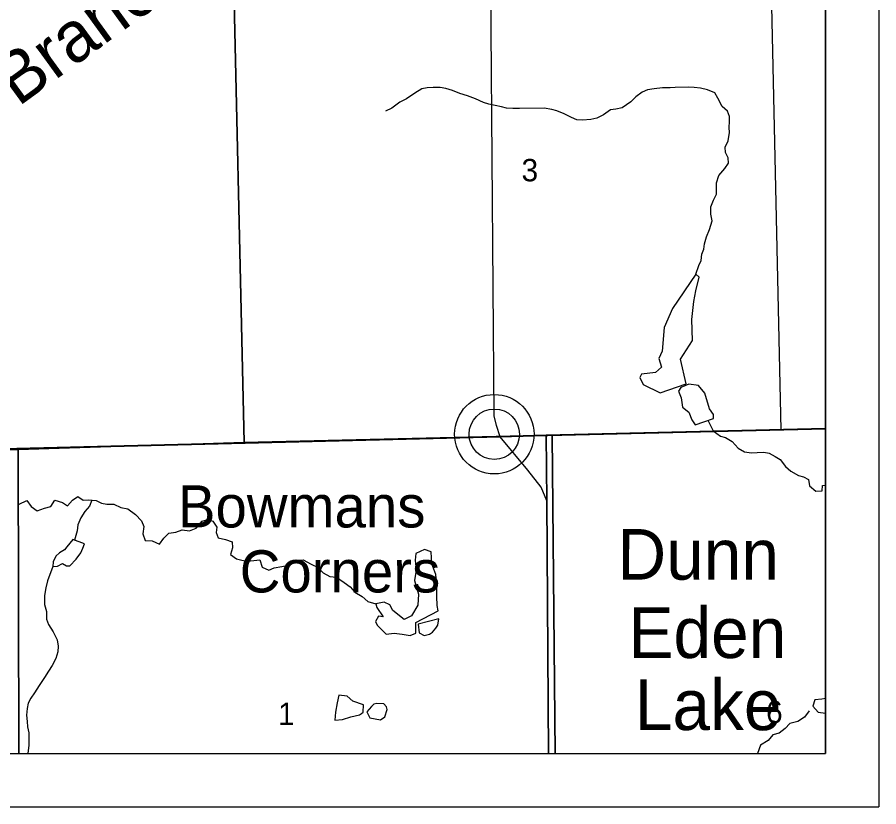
# Model space of a CAD drawing. Extents: x 0 to 34, y 0 to 22.
# Drawn here: x 8.73 to 10.344, y 13.024 to 14.503 of the extents above; entities that cross this region are included whole.
import ezdxf

# ---------------------------------------------------------------- set-up
doc = ezdxf.new("R2010")
doc.units = 0
for name, color, linetype in [('GM_X_Corporation', 7, 'Continuous'), ('GM_X_County_Road', 7, 'Continuous'), ('GM_X_Minor_Lake', 7, 'Continuous'), ('GM_X_Minor_Lake_Text', 7, 'Continuous'), ('GM_X_Minor_River', 7, 'Continuous'), ('GM_X_Minor_River_Text', 7, 'Continuous'), ('GM_X_Section_Text', 7, 'Continuous'), ('GM_X_State_Route', 7, 'Continuous'), ('GM_X_Unincorporated', 7, 'Continuous'), ('GM_X_Unincorporated_Location', 7, 'Continuous'), ('GM_X_Unincorporated_Text', 7, 'Continuous'), ('SH_Data', 7, 'Continuous')]:
    doc.layers.add(name, color=color, linetype=linetype)

msp = doc.modelspace()

# ---------------------------------------------------------------- linework, layer by layer
at = {"layer": 'GM_X_Corporation'}
msp.add_lwpolyline([(7.068, 16.109), (7.0714, 16.0063), (7.0745, 15.896), (7.0787, 15.766), (7.0827, 15.6404), (7.0859, 15.5239), (7.0914, 15.3396), (7.0961, 15.1801), (7.0965, 15.1593), (7.1012, 14.6522), (7.1045, 14.5502), (7.1291, 13.6578), (8.1719, 13.6806), (8.628, 13.6922), (9.6344, 13.7177), (9.7208, 13.7198), (10.2438, 13.7323), (10.2438, 18.8341)], dxfattribs=at)
for points in [[(10.2438, 13.7318), (10.2438, 14.7535), (10.1377, 14.7507), (10.1605, 13.7298)], [(9.132, 14.7248), (10.1377, 14.7507), (10.1605, 13.7298), (9.7319, 13.7196), (9.155, 13.7064)], [(8.1182, 14.6962), (9.132, 14.7248), (9.155, 13.7064), (8.7319, 13.6926), (8.142, 13.6801)], [(3.5203, 13.1239), (9.7254, 13.1239), (9.7218, 13.5975), (9.7208, 13.7198), (9.6344, 13.7177), (8.628, 13.6922), (8.1719, 13.6806), (7.1291, 13.6578), (7.1049, 13.6572), (5.8662, 13.6357), (5.5741, 13.6306), (4.9278, 13.619), (3.5133, 13.5939)], [(8.7329, 13.1239), (9.7377, 13.1239), (9.7319, 13.7196), (9.155, 13.7064), (8.7319, 13.6926)], [(9.7254, 13.1239), (10.2438, 13.1239), (10.2438, 13.7323), (9.7208, 13.7198), (9.7218, 13.5975)], [(9.7377, 13.1239), (10.2438, 13.1239), (10.2438, 13.7318), (10.1605, 13.7298), (9.7319, 13.7196)], [(7.6372, 13.1239), (8.7329, 13.1239), (8.7319, 13.6926), (8.142, 13.6801), (7.6279, 13.6693)]]:
    msp.add_lwpolyline(points, close=True, dxfattribs=at)
at = {"layer": 'GM_X_County_Road'}
msp.add_line((9.724, 13.7194), (10.2438, 13.7317), dxfattribs=at)
msp.add_lwpolyline([(8.6282, 13.6916), (9.6346, 13.7171), (9.721, 13.7193), (9.724, 13.7194)], dxfattribs=at)
at = {"layer": 'GM_X_Minor_Lake'}
for points in [[(9.9832, 13.8159), (9.9726, 13.8624), (9.9948, 13.8973), (9.9934, 13.9364), (9.9974, 13.9703), (10.0012, 13.9905), (10.0076, 14.0161), (10.0011, 14.0216), (9.9574, 13.9571), (9.9416, 13.9215), (9.9382, 13.8774), (9.9316, 13.8636), (9.9371, 13.8474), (9.9255, 13.8373), (9.8994, 13.8342), (9.8961, 13.8277), (9.9024, 13.8149), (9.9345, 13.7991)], [(9.9345, 13.7991), (9.9832, 13.8159)], [(10.034, 13.7514), (10.0343, 13.7586), (10.0269, 13.7691), (10.0177, 13.7986), (10.0064, 13.8128), (9.9882, 13.8156), (9.9731, 13.8089), (9.9686, 13.8023), (9.9738, 13.7899), (9.9764, 13.7721), (9.9883, 13.7628), (9.9938, 13.7484), (9.9997, 13.739)], [(9.9997, 13.739), (10.034, 13.7514)], [(8.834, 13.5244), (8.8228, 13.5109), (8.8184, 13.5052), (8.8093, 13.4993), (8.8022, 13.4935), (8.7971, 13.4824), (8.7965, 13.4737), (8.8052, 13.4746), (8.8146, 13.4796), (8.8223, 13.4752), (8.8287, 13.4753), (8.8403, 13.4877), (8.8492, 13.4996), (8.8529, 13.508), (8.8558, 13.5164)], [(8.8558, 13.5164), (8.834, 13.5244)], [(9.5184, 13.3908), (9.5163, 13.4011), (9.5157, 13.4178), (9.5161, 13.439), (9.5138, 13.4588), (9.5067, 13.4788), (9.5052, 13.5015), (9.4929, 13.5055), (9.4767, 13.498), (9.4751, 13.4859), (9.4773, 13.4673), (9.4742, 13.4475), (9.4814, 13.4221), (9.4802, 13.4012), (9.4684, 13.3817), (9.4545, 13.3746), (9.4337, 13.3917), (9.4279, 13.4019), (9.4175, 13.4074), (9.4016, 13.4041), (9.4036, 13.397), (9.4153, 13.3797), (9.4069, 13.3811), (9.401, 13.3707), (9.4042, 13.3639), (9.4208, 13.3471), (9.4359, 13.3489), (9.4508, 13.3472), (9.466, 13.3444), (9.4769, 13.3491), (9.4766, 13.3689)], [(9.4766, 13.3689), (9.5184, 13.3908)], [(9.4808, 13.3659), (9.483, 13.3496), (9.4922, 13.3445), (9.502, 13.3469), (9.5077, 13.3508), (9.514, 13.3581), (9.5177, 13.3639), (9.5194, 13.376)], [(9.5194, 13.376), (9.4808, 13.3659)], [(9.3785, 13.215), (9.3587, 13.2219), (9.3483, 13.2312), (9.3323, 13.2332), (9.3291, 13.2187), (9.326, 13.2008), (9.3251, 13.186), (9.3391, 13.1874), (9.3546, 13.1922), (9.3709, 13.1959)], [(9.3786, 13.215), (9.3587, 13.2219), (9.3483, 13.2312), (9.3323, 13.2332), (9.3291, 13.2187), (9.326, 13.2008), (9.3251, 13.186), (9.3391, 13.1874), (9.3546, 13.1922), (9.3709, 13.1959)], [(10.2438, 13.2268), (10.2371, 13.2252), (10.2242, 13.2242), (10.2202, 13.2124), (10.2303, 13.2011), (10.2438, 13.1994)], [(9.3709, 13.1959), (9.375, 13.1983), (9.3777, 13.2008), (9.3785, 13.215)], [(9.3934, 13.2114), (9.3849, 13.2014), (9.3903, 13.1905), (9.4105, 13.1866), (9.4188, 13.1925), (9.4231, 13.2058), (9.4219, 13.2111), (9.4165, 13.2167)], [(9.4165, 13.2167), (9.4033, 13.217), (9.3981, 13.2162), (9.3934, 13.2114)]]:
    msp.add_lwpolyline(points, dxfattribs=at)
at = {"layer": 'GM_X_Minor_River'}
for points in [[(10.0011, 14.0216), (10.0069, 14.0377), (10.0109, 14.0472), (10.0126, 14.0587), (10.0159, 14.0682), (10.0176, 14.0785), (10.0212, 14.0915), (10.027, 14.1049), (10.0317, 14.1213), (10.0292, 14.1338), (10.029, 14.1478), (10.0341, 14.1601), (10.0396, 14.1712), (10.0398, 14.1826), (10.0396, 14.1924), (10.044, 14.2066), (10.0555, 14.2197), (10.0622, 14.2296), (10.062, 14.2395), (10.0565, 14.2493), (10.056, 14.2596), (10.0619, 14.2714), (10.0639, 14.2866), (10.0634, 14.2965), (10.0643, 14.3072), (10.0645, 14.317), (10.0606, 14.3269), (10.0506, 14.3358), (10.0423, 14.3513), (10.0368, 14.3614), (10.0231, 14.3669), (10.0098, 14.3697), (9.9983, 14.3714), (9.9881, 14.3716), (9.9627, 14.3712), (9.9528, 14.3707), (9.9384, 14.3704), (9.9232, 14.3687), (9.9107, 14.367), (9.9009, 14.3626), (9.8889, 14.3537), (9.8792, 14.344), (9.8634, 14.3331), (9.8513, 14.3307), (9.8415, 14.329), (9.828, 14.32), (9.8156, 14.3138), (9.8046, 14.3109), (9.789, 14.3099), (9.778, 14.3105), (9.7681, 14.3149), (9.7547, 14.3219), (9.7409, 14.3277), (9.7314, 14.3302), (9.7169, 14.3327), (9.671, 14.3319), (9.6581, 14.3317), (9.6467, 14.3327), (9.6368, 14.3348), (9.6132, 14.3397), (9.6032, 14.343), (9.5883, 14.3496), (9.5734, 14.3554), (9.5593, 14.3601), (9.5452, 14.3656), (9.5326, 14.3692), (9.5219, 14.3709), (9.5094, 14.3714), (9.498, 14.3705), (9.4878, 14.3684), (9.475, 14.3606), (9.4593, 14.3497), (9.4468, 14.3435), (9.4318, 14.3322), (9.4198, 14.3267)], [(10.0238, 13.7477), (10.0333, 13.7278), (10.0471, 13.7181), (10.0566, 13.7153), (10.0689, 13.7079), (10.0805, 13.6955), (10.0924, 13.6885), (10.1057, 13.6868), (10.1163, 13.6877), (10.1285, 13.6879), (10.1387, 13.6862), (10.1495, 13.6799), (10.1591, 13.6744), (10.1688, 13.6612), (10.1788, 13.6523), (10.1933, 13.6446), (10.2029, 13.6417), (10.2124, 13.6369), (10.2138, 13.6248), (10.2261, 13.6151), (10.2375, 13.6156), (10.2381, 13.6259), (10.2438, 13.626)], [(8.7334, 13.5904), (8.7477, 13.5978), (8.7563, 13.5862), (8.7674, 13.578), (8.781, 13.5832), (8.7931, 13.586), (8.8005, 13.5979), (8.8146, 13.594), (8.8242, 13.5873), (8.8335, 13.5981), (8.8437, 13.6051), (8.8533, 13.5984), (8.8628, 13.5986), (8.8776, 13.5977), (8.8875, 13.5925), (8.8978, 13.5908), (8.9111, 13.5906), (8.9241, 13.5844), (8.9374, 13.5819), (8.9517, 13.5711), (8.9629, 13.5592), (8.9672, 13.5486), (8.9655, 13.5353), (8.9699, 13.5228), (8.9825, 13.5219), (8.9962, 13.516), (9.0044, 13.5268), (9.0141, 13.5361), (9.027, 13.5382), (9.0391, 13.5429), (9.0524, 13.5405), (9.0652, 13.546), (9.0764, 13.5587), (9.087, 13.562), (9.0965, 13.5591), (9.1039, 13.5478), (9.1025, 13.5379), (9.1061, 13.5273), (9.1198, 13.5245), (9.1328, 13.5202), (9.133, 13.5091), (9.1294, 13.4966), (9.1409, 13.488), (9.1509, 13.4855), (9.1604, 13.4841), (9.1733, 13.4851), (9.1846, 13.4861), (9.189, 13.4728), (9.2013, 13.4673), (9.2111, 13.4717), (9.2255, 13.4742), (9.2357, 13.4759), (9.2522, 13.4856), (9.2655, 13.4862), (9.2804, 13.4781), (9.2938, 13.4719), (9.3031, 13.4622), (9.3157, 13.4552), (9.3283, 13.4538), (9.3425, 13.4438), (9.3536, 13.436), (9.3625, 13.4259), (9.376, 13.4178), (9.3864, 13.4081), (9.4016, 13.4041)], [(8.8697, 13.5981), (8.8656, 13.5872), (8.8567, 13.5768), (8.8493, 13.5653), (8.8434, 13.5519), (8.8424, 13.5409), (8.8372, 13.5232)], [(8.7965, 13.4737), (8.7867, 13.4473), (8.7835, 13.4339), (8.7811, 13.4198), (8.7813, 13.4028), (8.785, 13.3899), (8.7848, 13.3751), (8.7884, 13.3653), (8.797, 13.3514), (8.8045, 13.3363), (8.8069, 13.3246), (8.806, 13.3143), (8.8024, 13.3017), (8.7954, 13.2883), (8.7883, 13.2779), (8.7809, 13.266), (8.7713, 13.251), (8.7621, 13.2372), (8.7554, 13.2272), (8.7506, 13.2177), (8.7485, 13.2081), (8.7476, 13.1952), (8.7485, 13.1838), (8.7494, 13.1736), (8.7515, 13.1626), (8.7517, 13.1504), (8.7515, 13.1387), (8.7506, 13.1292), (8.7498, 13.1239)], [(10.2135, 13.2035), (10.2046, 13.192), (10.1922, 13.1834), (10.1775, 13.1801), (10.1685, 13.1705), (10.1573, 13.1616), (10.1456, 13.1587), (10.1366, 13.148), (10.1223, 13.1394), (10.1164, 13.1239)]]:
    msp.add_lwpolyline(points, dxfattribs=at)
at = {"layer": 'GM_X_State_Route'}
for points in [[(9.618, 14.4794), (9.6162, 14.7175), (9.6161, 14.8467)], [(9.6346, 13.7171), (9.6278, 13.7378), (9.6234, 13.756), (9.618, 14.4794)], [(9.7256, 13.1239), (9.722, 13.5969), (9.7111, 13.6222), (9.6867, 13.6541), (9.6346, 13.7171)]]:
    msp.add_lwpolyline(points, dxfattribs=at)
at = {"layer": 'GM_X_Unincorporated'}
for radius in [0.0744, 0.0472]:
    msp.add_circle((9.6236, 13.7217), radius, dxfattribs=at)
at = {"layer": 'GM_X_Unincorporated_Location'}
msp.add_line((9.6236, 13.7217), (9.6236, 13.7217), dxfattribs=at)
at = {"layer": 'SH_Data'}
for p, q in [((10.3438, 20.0239), (10.3438, 13.0239)), ((10.2438, 19.9239), (10.2438, 13.1239)), ((3.4438, 13.1239), (10.2438, 13.1239)), ((3.3438, 13.0239), (10.3438, 13.0239))]:
    msp.add_line(p, q, dxfattribs=at)

# ---------------------------------------------------------------- texts
at = {"layer": 'GM_X_Minor_Lake_Text'}
for s, rotation, p in [('Dunn', 359.9565, (9.854, 13.4494)), ('Eden', 359.9566, (9.8747, 13.3026)), ('Lake', 359.9567, (9.8869, 13.1676))]:
    msp.add_text(s, height=0.09473, rotation=rotation, dxfattribs=at).set_placement(p)
at = {"layer": 'GM_X_Minor_River_Text'}
msp.add_text('Branch', height=0.09473, rotation=35.9921, dxfattribs=at).set_placement((8.7316, 14.3341))
at = {"layer": 'GM_X_Section_Text'}
for s, p in [('3', (9.6746, 14.1954)), ('1', (9.2184, 13.1771)), ('6', (10.1326, 13.1804))]:
    msp.add_text(s, height=0.0419, rotation=0, dxfattribs=at).set_placement(p)
at = {"layer": 'GM_X_Unincorporated_Text'}
for s, p in [('Bowmans', (9.0309, 13.547)), ('Corners', (9.1467, 13.4253))]:
    msp.add_text(s, height=0.07898, rotation=0, dxfattribs=at).set_placement(p)

doc.saveas('drawing.dxf')
